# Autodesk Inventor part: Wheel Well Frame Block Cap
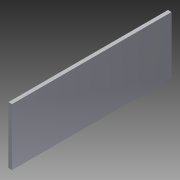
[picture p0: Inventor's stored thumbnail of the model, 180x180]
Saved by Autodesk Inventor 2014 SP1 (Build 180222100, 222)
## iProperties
Created: 2014-11
Part Number: Wheel Well Frame Block Cap
Material: Aluminum 6061
Document SubType Name: Sheet Metal
Designer: Michael
Density: 2.71 g/cm^3
Sheet Metal Rule: Default
Appearance: Aluminum - Flat
Author: Michael
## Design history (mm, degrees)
node "Face1"
  sketch "Sketch1"
    geometry: L1 (-12.7, -35.498)-(12.7, -35.498); L2 (12.7, -35.498)-(12.7, 35.498); L3 (12.7, 35.498)-(-12.7, 35.498); L4 (-12.7, 35.498)-(-12.7, -35.498); L5 (-12.7, -35.498)-(12.7, 35.498); L6 (12.7, -35.498)-(-12.7, 35.498); 1 further point
    constraints: 12 end point, 2 midpoint, 2 parallel, 1 horizontal, 1 perpendicular
    dimensions: "d0" = 25.4 distance of L3.end L2.end; "d1" = 70.99516 distance between parallel lines of L1 L3
body "Solid1"
face "Plate1" dims "Thickness" = 1.5875 (derived)
other parameters: "KFactor" = 4.4, "BendRadius" = 1.5875 (= Thickness), "BendReliefWidth" = 1.5875 (= Thickness), "BendReliefDepth" = 0.79375 (= 0.5 x Thickness), "CornerReliefSize" = 6.35 (= 4 x Thickness), "SeamGap" = 0.00508, "MinimumRemnant" = 3.175 (= 2 x Thickness), "TransitionRadius" = 1.5875 (= BendRadius), "JacobiRadiusSize" = 1.5875 (= Thickness), "GapSize" = 1.5875 (= Thickness), "d2" = 1.5875 (= BendRadius)
